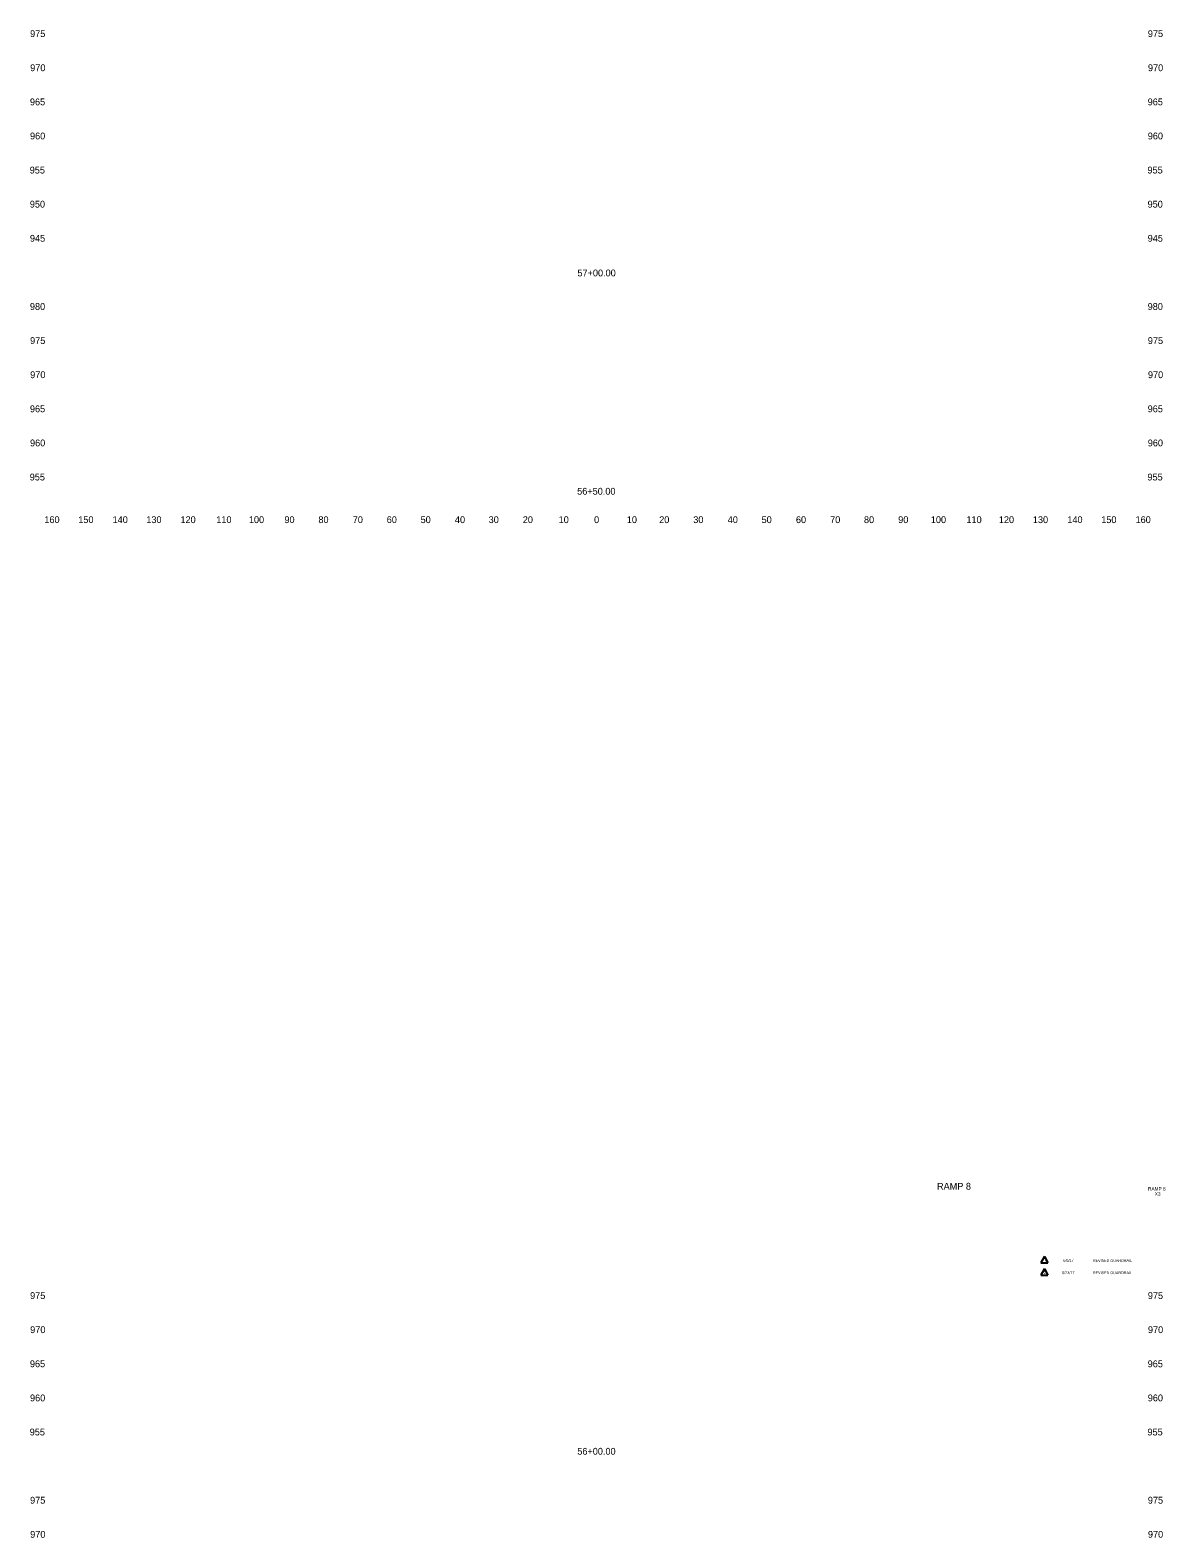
# Model space of a CAD drawing. Extents: x 4994 to 5843, y 4997 to 8804.
# Drawn here: x 4993.9 to 5326.7, y 5900 to 6342 of the extents above; entities that cross this region are included whole.
import ezdxf

# ---------------------------------------------------------------- set-up
doc = ezdxf.new("R2010")
doc.units = 0
for name, color, linetype in [('RD_SHT_ID', 7, 'Continuous'), ('RD_SHT_TX', 7, 'Continuous'), ('RD_XS_TX_Offset', 7, 'Continuous'), ('RD_XS_TX_Station', 7, 'Continuous')]:
    doc.layers.add(name, color=color, linetype=linetype)

msp = doc.modelspace()

# ---------------------------------------------------------------- linework, layer by layer
at = {"layer": 'RD_SHT_TX'}
for p, q in [((5291.4, 5982.45), (5290.37, 5980.62)), ((5291.4, 5982.45), (5292.42, 5980.62)), ((5290.37, 5980.62), (5292.42, 5980.62)), ((5291.4, 5978.86), (5290.37, 5977.03)), ((5290.37, 5977.03), (5292.42, 5977.03)), ((5291.4, 5978.86), (5292.42, 5977.03))]:
    msp.add_line(p, q, dxfattribs=at)

# ---------------------------------------------------------------- texts
at = {"layer": 'RD_SHT_ID'}
for s, height, p in [('RAMP 8', 2, (5259.88, 6002.06)), ('RAMP 8', 1, (5321.78, 6001.8)), ('X3', 1, (5323.74, 6000.3))]:
    msp.add_text(s, height=height, dxfattribs=at).set_placement(p)
at = {"layer": 'RD_SHT_TX'}
for s, p in [('1', (5291.4, 5980.91)), ('6/6/17', (5296.9, 5980.88)), ('REVISED GUARDRAIL', (5305.6, 5980.88)), ('2', (5291.17, 5977.32)), ('6/23/17', (5296.56, 5977.29)), ('REVISED GUARDRAIL', (5305.6, 5977.29))]:
    msp.add_text(s, height=0.792, dxfattribs=at).set_placement(p)
at = {"layer": 'RD_XS_TX_Offset'}
for s, p in [('975', (4993.91, 6340)), ('975', (5321.71, 6340)), ('970', (4993.94, 6330)), ('970', (5321.74, 6330)), ('965', (4993.86, 6320)), ('965', (5321.66, 6320)), ('960', (4993.89, 6310)), ('960', (5321.69, 6310)), ('955', (4993.8, 6300)), ('955', (5321.6, 6300)), ('950', (4993.83, 6290)), ('950', (5321.63, 6290)), ('945', (4993.86, 6280)), ('945', (5321.66, 6280)), ('980', (4993.86, 6260)), ('980', (5321.66, 6260)), ('975', (4993.91, 6250)), ('975', (5321.71, 6250)), ('970', (4993.94, 6240)), ('970', (5321.74, 6240)), ('965', (4993.86, 6230)), ('965', (5321.66, 6230)), ('960', (4993.89, 6220)), ('960', (5321.69, 6220)), ('955', (4993.8, 6210)), ('955', (5321.6, 6210)), ('160', (4998.1, 6197.5)), ('150', (5008.04, 6197.5)), ('140', (5018.1, 6197.5)), ('130', (5027.99, 6197.5)), ('120', (5038.01, 6197.5)), ('110', (5048.51, 6197.5)), ('100', (5058.07, 6197.5)), ('90', (5068.5, 6197.5)), ('80', (5078.46, 6197.5)), ('70', (5088.54, 6197.5)), ('60', (5098.5, 6197.5)), ('50', (5108.43, 6197.5)), ('40', (5118.5, 6197.5)), ('30', (5128.39, 6197.5)), ('20', (5138.4, 6197.5)), ('10', (5148.91, 6197.5)), ('0', (5159.3, 6197.5)), ('0', (5159.3, 6197.5)), ('10', (5168.91, 6197.5)), ('20', (5178.4, 6197.5)), ('30', (5188.39, 6197.5)), ('40', (5198.5, 6197.5)), ('50', (5208.43, 6197.5)), ('60', (5218.5, 6197.5)), ('70', (5228.54, 6197.5)), ('80', (5238.46, 6197.5)), ('90', (5248.5, 6197.5)), ('100', (5258.07, 6197.5)), ('110', (5268.51, 6197.5)), ('120', (5278.01, 6197.5)), ('130', (5287.99, 6197.5)), ('140', (5298.1, 6197.5)), ('150', (5308.04, 6197.5)), ('160', (5318.1, 6197.5)), ('975', (4993.91, 5970)), ('975', (5321.71, 5970)), ('970', (4993.94, 5960)), ('970', (5321.74, 5960)), ('965', (4993.86, 5950)), ('965', (5321.66, 5950)), ('960', (4993.89, 5940)), ('960', (5321.69, 5940)), ('955', (4993.8, 5930)), ('955', (5321.6, 5930)), ('975', (4993.91, 5910)), ('975', (5321.71, 5910)), ('970', (4993.94, 5900)), ('970', (5321.74, 5900))]:
    msp.add_text(s, height=2, dxfattribs=at).set_placement(p)
at = {"layer": 'RD_XS_TX_Station'}
for s, p in [('57+00.00', (5154.43, 6269.84)), ('56+50.00', (5154.35, 6205.83)), ('56+00.00', (5154.39, 5924.35))]:
    msp.add_text(s, height=2, dxfattribs=at).set_placement(p)

doc.saveas('drawing.dxf')
